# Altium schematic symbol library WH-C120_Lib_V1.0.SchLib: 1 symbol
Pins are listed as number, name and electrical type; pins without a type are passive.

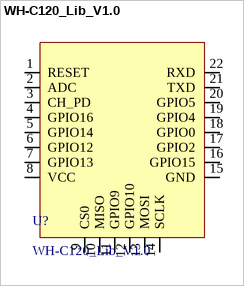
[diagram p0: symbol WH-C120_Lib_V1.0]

## WH-C120_Lib_V1.0
designator U?
pins: 1 RESET, 2 ADC, 3 CH_PD, 4 GPIO16, 5 GPIO14, 6 GPIO12, 7 GPIO13, 8 VCC, 9 CS0, 10 MISO, 11 GPIO9, 12 GPIO10, 13 MOSI, 14 SCLK, 15 GND, 16 GPIO15, 17 GPIO2, 18 GPIO0, 19 GPIO4, 20 GPIO5, 21 TXD, 22 RXD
